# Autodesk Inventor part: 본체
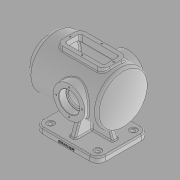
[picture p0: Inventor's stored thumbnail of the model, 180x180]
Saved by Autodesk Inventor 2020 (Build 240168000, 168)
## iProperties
Created: 2021-11
Part Number: 본체
Material: 일반
Document SubType Name: Modeling
Designer: Administrator
Density: 1 g/cm^3
Appearance: 기본값
Mass: 1310.49 g
Surface Area: 2409.35 cm^2
Volume: 1310.49 cm^3
Author: Administrator
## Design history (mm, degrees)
sketch "스케치1"
  geometry: L1 (-80, 65)-(80, 65); L2 (80, 65)-(80, -65); L3 (80, -65)-(-80, -65); L4 (-80, -65)-(-80, 65); L5 (-80, 65)-(80, -65); L6 (80, 65)-(-80, -65); 1 further point
  constraints: 12 end point, 2 midpoint, 2 parallel, 1 horizontal, 1 perpendicular
  dimensions: "d0" = 160 distance of L2.end L3.end; "d1" = 130 distance of L1.end L2.end
extrude "돌출1" new body sketch "스케치1" distance "d2" = 14; taper "d3" = 0 deg
sketch "스케치2"
  geometry: L1 (110, 114)-(110, 161.5); L2 (110, 161.5)-(100, 161.5); L3 (100, 161.5)-(100, 179); L4 (100, 179)-(-75.993, 179); L5 (110, 114)-(-100, 114); L6 (80, 0)-(80, 14) reference; L7 (85, 169)-(-71.239, 169); L8 (110, 146.5)-(85, 146.5); L9 (85, 146.5)-(85, 169); A1 r 100 centre (0, 114) between (-75.993, 179) and (-100, 114); A2 r 90 centre (0, 114) between (-71.239, 169) and (-90, 114); 2 further points
  constraints: 16 end point, 4 perpendicular, 4 point on circle, 2 centre point, 2 horizontal, 2 point on line, 1 horizontal alignment, 1 midpoint, 1 vertical
  dimensions: "d4" = 210 distance of L1.start L5.end; "d5" = 95 diameter of L2 L5; "d6" = 130 diameter of L4 L5; "d7" = 100 radius of A1; "d8" = 10 distance between parallel lines of L1 L3; "d9" = 114 vertical distance of L1.start point (0, 0); "d10" = 30 distance between parallel lines of L1 L6; "d11" = 10 radial gap between concentric circles of A1 A2; "d12" = 65 diameter of L8 L5; "d13" = 25 distance between parallel lines of L9 L1; "d14" = 110 diameter of L7 L5
revolve "회전1" sketch "스케치2" stored, may be unused: angle "d15" = 90 deg
sketch "스케치3"
  geometry: L1 (-7, 7)-(7, 7); L2 (7, 7)-(7, -7); L3 (7, -7)-(-7, -7); L4 (-7, -7)-(-7, 7); L5 (-7, 7)-(7, -7); L6 (7, 7)-(-7, -7); 1 further point
  constraints: 12 end point, 2 midpoint, 2 parallel, 1 horizontal, 1 perpendicular
  dimensions: "d16" = 14 distance of L2.end L3.end; "d17" = 14 distance of L1.end L2.end
extrude "돌출2" join sketch "스케치3" stored distance "d18" = 14; taper "d19" = 0 deg
sketch "스케치4"
  geometry: L1 (-80, 14)-(80, 14) reference; L2 (-60, 14)-(-51.998, 35.984); 1 further point
  constraints: 2 end point, 1 point on line
  dimensions: "d20" = 60 horizontal distance of L2.start point (0, 0); "d21" = 110 deg angle of L2 L1
feature "리브1" sketch "스케치4" dims "d22" = 1, "d23" = 14, "d24" = 0, "d25" = 0, "d26" = 1, "d27" = 1
sketch "스케치5"
  geometry: L1 (65, 14)-(-65, 14) reference; L2 (50, 14)-(39.5, 42.849); 1 further point
  constraints: 2 end point, 1 point on line
  dimensions: "d28" = 50 horizontal distance of L2.start point (0, 0); "d29" = 110 deg angle of L1 L2
feature "리브2" sketch "스케치5" dims "d30" = 1, "d31" = 14, "d32" = 0, "d33" = 0, "d34" = 1, "d35" = 1
node "작업 평면1"
sketch "스케치6"
  geometry: L1 (-60, 30)-(60, 30); L2 (60, 30)-(60, -30); L3 (60, -30)-(-60, -30); L4 (-60, -30)-(-60, 30); L5 (-110, 47.5)-(-110, -47.5) reference; 3 further points
  constraints: 8 end point, 2 horizontal alignment, 2 midpoint, 2 parallel, 1 horizontal, 1 perpendicular
  dimensions: "d37" = 60 distance between parallel lines of L3 L1; "d38" = 120 distance between parallel lines of L2 L4; "d39" = 50 distance between parallel lines of L4 L5
extrude "돌출3" join sketch "스케치6" stored distance "d40" = 14; taper "d41" = 0 deg
sketch "스케치7"
  geometry: L1 (60, 30)-(-60, 30) reference; L2 (-60, 30)-(-60, -30) reference; L3 (-60, -30)-(60, -30) reference; L4 (60, -30)-(60, 30) reference; L5 (-50, 20)-(50, 20); L6 (50, 20)-(50, -20); L7 (50, -20)-(-50, -20); L8 (-50, -20)-(-50, 20); 1 further point
  constraints: 8 end point, 3 other
  dimensions: "d42" = 10 distance between parallel lines of L1 L5
extrude "돌출4" cut sketch "스케치7" stored distance "d43" = 14; taper "d44" = 0 deg
node "작업 평면2"
sketch "스케치8"
  geometry: L1 (-110, 161.5)-(-110, 66.5) reference; C1 r 40 at (17, 114); 2 further points
  constraints: 1 centre point, 1 horizontal alignment, 1 midpoint
  dimensions: "d46" = 80 diameter of C1; "d47" = 127 distance from line of L1 C1.centre
extrude "돌출5" join sketch "스케치8" stored distance "d48" = 14; taper "d49" = 0 deg
sketch "스케치9"
  geometry: C1 r 40 at (0, 0) reference; C2 r 26 at (0, 0); 1 further point
  constraints: 1 centre point, 1 coincident
  dimensions: "d50" = 52 diameter of C2
extrude "돌출6" cut sketch "스케치9" distance "d51" = 18; taper "d52" = 0 deg
sketch "스케치10"
  geometry: C1 r 26 at (0, 0) reference; C2 r 21 at (0, 0); 1 further point
  constraints: 1 centre point, 1 coincident
  dimensions: "d53" = 42 diameter of C2
extrude "돌출7" cut sketch "스케치10" extent not by distance; stored distance "d54" = 18; taper "d55" = 0 deg
sketch "스케치11" dims "d56" = 65
  geometry: L1 (0, 0)-(0, 32.5); C1 r 26 at (0, 0) reference; 2 further points
  constraints: 2 coincident, 2 end point, 1 vertical, 1 vertical alignment, 2 other
hole "구멍1" sketch "스케치11" at (0, 32.5) diameter "d57" = 3.45873; stored, may be unused: countersink angle "d61" = 90 deg, drill point angle "d63" = 118 deg; dims "d58" = 11, "d59" = 4, "d60" = 2, "d62" = 13
fillet "모깎기1" dims "d67" = 20
sketch "스케치12"
  geometry: A1 r 20 centre (60, 45) between (80, 45) and (60, 65) reference; A2 r 20 centre (-60, 45) between (-60, 65) and (-80, 45) reference; A3 r 20 centre (-60, -45) between (-80, -45) and (-60, -65) reference; A4 r 20 centre (60, -45) between (60, -65) and (80, -45) reference; 5 further points
  constraints: 4 coincident
hole "구멍2" sketch "스케치12" at (60, 45), (-60, 45), (-60, -45), (60, -45) diameter "d68" = 9; stored, may be unused: countersink angle "d72" = 90 deg, drill point angle "d74" = 118 deg; dims "d69" = 11, "d70" = 18, "d71" = 2, "d73" = 13
fillet "모깎기2" dims "d75" = 3
fillet "모깎기3" dims "d76" = 3
fillet "모깎기4" dims "d77" = 10
fillet "모깎기5" dims "d78" = 3
fillet "모깎기6" dims "d79" = 3
fillet "모깎기7" dims "d80" = 15
fillet "모깎기8" dims "d81" = 5
fillet "모깎기9" dims "d82" = 3
sketch "스케치13"
  geometry: L1 (-23, 75)-(57, 75) reference; L2 (17, 75)-(17, 84.959); L3 (-45, 20)-(45, 20) reference; L4 (45, -20)-(-45, -20) reference; 5 further points
  constraints: 2 end point, 2 horizontal alignment, 1 midpoint, 1 vertical
  dimensions: "d83" = 50 distance of point (0, -25) point (0, 25); "d84" = 17 distance from line of point (0, 25) L2; "d85" = 5 distance from line of point (0, 25) L3; "d86" = 5 distance from line of L4 point (0, -25); "d87" = 55 horizontal distance of point (-55, 0) point (0, 25); "d88" = 55 horizontal distance of point (0, 25) point (55, 0)
hole "구멍3" sketch "스케치13" at (0, 25), (0, -25), (55, 0), (-55, 0) diameter "d89" = 3.45873; stored, may be unused: countersink angle "d93" = 90 deg, drill point angle "d95" = 118 deg; dims "d90" = 9, "d91" = 18, "d92" = 2, "d94" = 11
fillet "모깎기10" dims "d96" = 3
chamfer "모따기1" distance "d97" = 1; stored, may be unused: second distance "d98" = 2, angle "d99" = 45 deg
chamfer "모따기2" distance "d100" = 1; stored, may be unused: second distance "d101" = 2, angle "d102" = 45 deg
fillet "모깎기11" dims "d103" = 0.3
sketch "스케치14"
  geometry: L1 (39.261, 8.002)-(80.739, 8.002); L2 (80.739, 8.002)-(80.739, 1.998); L3 (80.739, 1.998)-(39.261, 1.998); L4 (39.261, 1.998)-(39.261, 8.002); L5 (39.261, 8.002)-(80.739, 1.998); L6 (0, 0)-(120, 0) reference; 3 further points
  constraints: 2 end point, 2 midpoint, 1 vertical alignment, 2 other
  dimensions: "d104" = 5 distance from line of point (60, 5) L6
feature "엠보싱1" sketch "스케치14" dims "d4" = 210, "d5" = 95, "d6" = 130, "d7" = 100, "d8" = 10, "d9" = 114, "d10" = 30, "d11" = 10, "d12" = 65, "d13" = 25, "d14" = 110, "d105" = 0.5, "d106" = 0
sketch "스케치15" dims "d107" = 80
  geometry: L1 (0, 0)-(40, 0); C1 r 47.5 at (0, 0) reference; 2 further points
  constraints: 2 coincident, 2 end point, 1 horizontal, 1 horizontal alignment, 2 other
hole "구멍4" sketch "스케치15" at (40, 0) diameter "d108" = 3.45873; stored, may be unused: countersink angle "d112" = 90 deg, drill point angle "d114" = 118 deg; dims "d109" = 11, "d110" = 18, "d111" = 2, "d113" = 13
fillet "모깎기12" dims "d118" = 3
node "솔리드1"
mirror "미러1"
mirror "미러2"
mirror "미러3"
mirror "미러4"
pattern_circular "원형 패턴1" dims angle "d65" = 360 deg
mirror "미러5"
pattern_circular "원형 패턴2" dims angle "d116" = 360 deg
node "투영된 루프1"
node "투영된 루프2"
feature "A9D066F2-1C7D-4E18-AEED-F7BC21143FA4" dims "d68" = 9, "d69" = 11, "d70" = 18, "d71" = 2, "d72" = 90 deg, "d73" = 13, "d74" = 118 deg
other parameters: "d36" = 184, "d45" = -75
